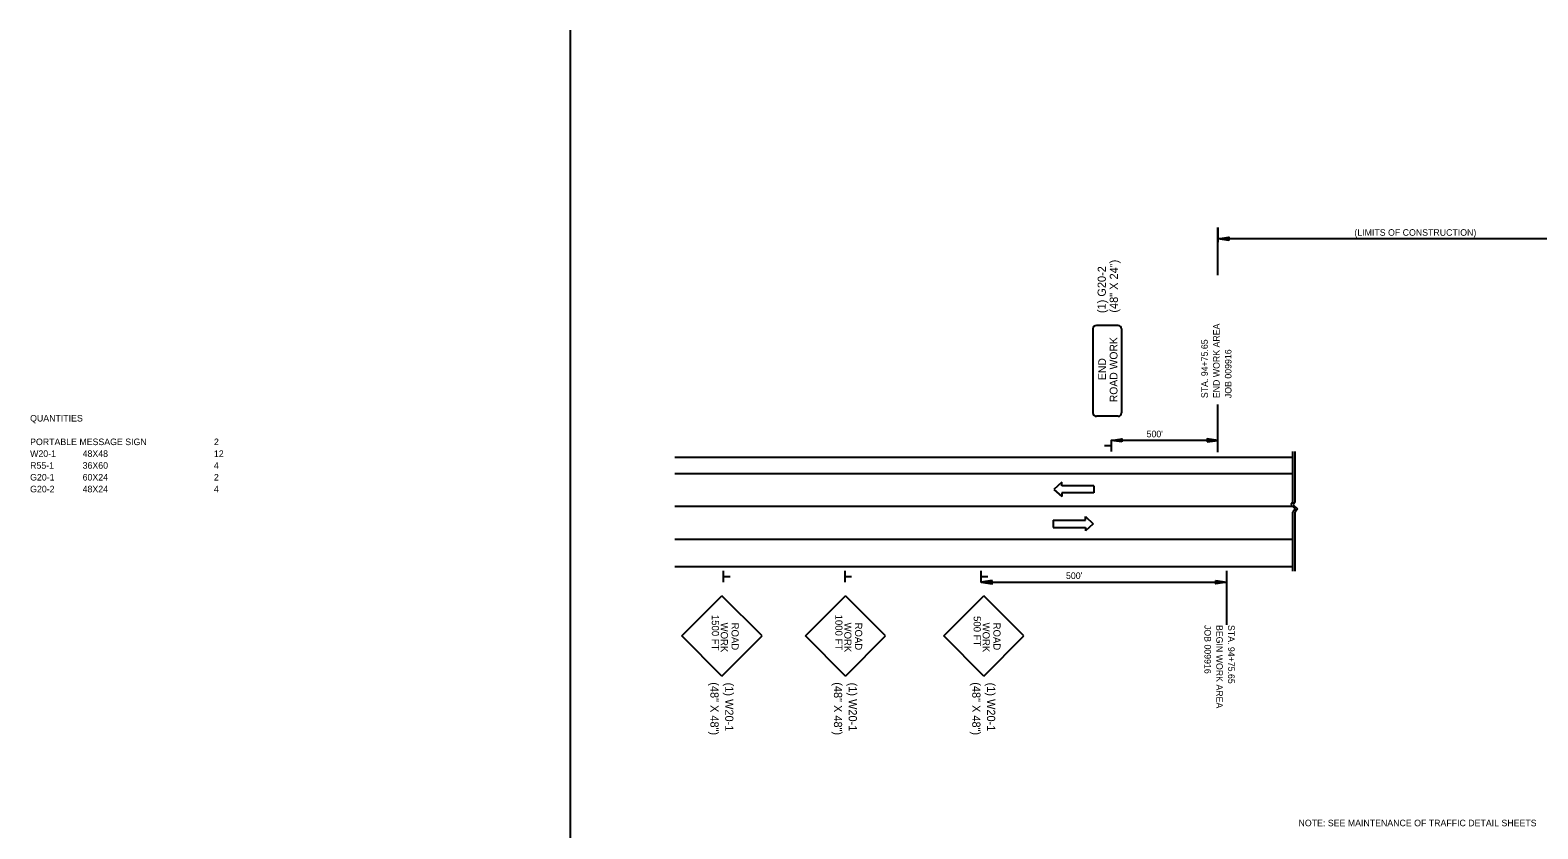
# Model space of a CAD drawing. Extents: x -900 to -62, y -12423 to -11428.
# Drawn here: x -900 to -349, y -12134 to -11842 of the extents above; entities that cross this region are included whole.
import ezdxf

# ---------------------------------------------------------------- set-up
doc = ezdxf.new("R2010")
doc.units = 0
for name, color, linetype in [('1', 7, 'Continuous'), ('Level 1', 7, 'Continuous'), ('R_MOT', 7, 'Continuous')]:
    doc.layers.add(name, color=color, linetype=linetype)

msp = doc.modelspace()

# ---------------------------------------------------------------- linework, layer by layer
at = {"layer": '1'}
for p, q in [((-465.9, -11931.22), (-465.9, -11913.78)), ((-465.9, -11913.78), (-465.9, -11919.03)), ((-319.31, -11917.87), (-465.9, -11917.87)), ((-465.9, -11995.93), (-465.9, -11978.49)), ((-465.9, -11991.59), (-504.98, -11991.59)), ((-504.97, -11991.61), (-504.97, -11995.67)), ((-664.49, -11997.69), (-438.5, -11997.69)), ((-504.97, -11993.64), (-507.34, -11993.64)), ((-438.5, -12014.03), (-438.5, -11995.69)), ((-437.63, -12014.03), (-437.63, -11995.69)), ((-664.49, -12003.69), (-438.5, -12003.69)), ((-438.5, -12014.03), (-439.26, -12015.18)), ((-439.26, -12015.18), (-437.73, -12016.71)), ((-437.63, -12014.03), (-438.39, -12015.18)), ((-438.39, -12015.18), (-436.86, -12016.71)), ((-664.49, -12015.69), (-438.75, -12015.69)), ((-437.73, -12016.71), (-438.5, -12017.85)), ((-438.5, -12039.43), (-438.5, -12017.85)), ((-436.86, -12016.71), (-437.63, -12017.85)), ((-437.63, -12039.43), (-437.63, -12017.85)), ((-664.49, -12027.69), (-438.5, -12027.69)), ((-664.49, -12037.69), (-438.5, -12037.69)), ((-646.62, -12043.42), (-646.62, -12039.36)), ((-646.62, -12041.39), (-644.26, -12041.39)), ((-602.22, -12043.42), (-602.22, -12039.36)), ((-602.22, -12041.39), (-599.86, -12041.39)), ((-552.45, -12043.42), (-552.45, -12039.36)), ((-552.45, -12041.39), (-550.09, -12041.39)), ((-462.72, -12059.14), (-462.72, -12039.36)), ((-552.45, -12043.43), (-462.72, -12043.43))]:
    msp.add_line(p, q, dxfattribs=at)
for points in [[(-461.94, -11918.47), (-465.9, -11917.87), (-461.94, -11917.27)], [(-501.02, -11992.19), (-504.98, -11991.59), (-501.02, -11990.99)], [(-469.86, -11992.19), (-465.9, -11991.59), (-469.86, -11990.99)], [(-548.49, -12042.83), (-552.45, -12043.43), (-548.49, -12044.03)], [(-466.68, -12042.83), (-462.72, -12043.43), (-466.68, -12044.03)]]:
    msp.add_lwpolyline(points, close=True, dxfattribs=at)
at = {"layer": 'Level 1'}
msp.add_line((-702.63, -12252.44), (-702.63, -11841.52), dxfattribs=at)
at = {"layer": 'R_MOT'}
for p, q in [((-511.6, -11950.84), (-511.6, -11981.55)), ((-502.42, -11949.59), (-510.35, -11949.59)), ((-501.17, -11950.84), (-501.17, -11981.55)), ((-502.42, -11982.8), (-510.35, -11982.8)), ((-522.99, -12006.93), (-525.87, -12009.54)), ((-525.87, -12009.54), (-522.99, -12012.16)), ((-522.99, -12008.24), (-522.99, -12006.93)), ((-511.24, -12008.24), (-522.99, -12008.24)), ((-511.24, -12008.24), (-511.24, -12010.85)), ((-511.24, -12010.85), (-522.99, -12010.85)), ((-522.99, -12010.85), (-522.99, -12012.16)), ((-526.14, -12020.81), (-514.39, -12020.81)), ((-526.14, -12020.81), (-526.14, -12023.43)), ((-514.39, -12020.81), (-514.39, -12019.51)), ((-514.39, -12019.51), (-511.52, -12022.12)), ((-526.14, -12023.43), (-514.39, -12023.43)), ((-511.52, -12022.12), (-514.39, -12024.74)), ((-514.39, -12023.43), (-514.39, -12024.74)), ((-661.87, -12063.15), (-647.23, -12048.49)), ((-632.57, -12063.15), (-647.23, -12048.49)), ((-616.72, -12063.15), (-602.07, -12048.49)), ((-587.41, -12063.15), (-602.07, -12048.49)), ((-566.15, -12063.15), (-551.5, -12048.49)), ((-536.84, -12063.15), (-551.5, -12048.49)), ((-647.23, -12077.81), (-661.87, -12063.15)), ((-647.23, -12077.81), (-632.57, -12063.15)), ((-602.07, -12077.81), (-616.72, -12063.15)), ((-602.07, -12077.81), (-587.41, -12063.15)), ((-551.5, -12077.81), (-566.15, -12063.15)), ((-551.5, -12077.81), (-536.84, -12063.15))]:
    msp.add_line(p, q, dxfattribs=at)
for centre, start, end in [((-510.35, -11950.84), 90.0014, 180.0003), ((-502.42, -11950.84), 0.0003, 90.0014), ((-510.35, -11981.55), 180.0003, 270.0014), ((-502.42, -11981.55), 270.0014, 0.0003)]:
    msp.add_arc(centre, 1.25, start, end, dxfattribs=at)

# ---------------------------------------------------------------- texts
at = {"layer": '1'}
for s, p in [('(LIMITS OF CONSTRUCTION)', (-416.03, -11916.75)), ('QUANTITIES', (-900.15, -11984.7)), ('PORTABLE MESSAGE SIGN', (-900.15, -11993.34)), ('2', (-832.95, -11993.34)), ("500'", (-492, -11990.47)), ('W20-1', (-900.15, -11997.66)), ('48X48', (-880.95, -11997.66)), ('12', (-832.95, -11997.66)), ('G20-1', (-900.15, -12006.3)), ('R55-1', (-900.15, -12001.98)), ('36X60', (-880.95, -12001.98)), ('60X24', (-880.95, -12006.3)), ('4', (-832.95, -12001.98)), ('2', (-832.95, -12006.3)), ('G20-2', (-900.15, -12010.62)), ('48X24', (-880.95, -12010.62)), ('4', (-832.95, -12010.62)), ('NOTE: SEE MAINTENANCE OF TRAFFIC DETAIL SHEETS', (-436.45, -12132.78))]:
    msp.add_text(s, height=2.4, dxfattribs=at).set_placement(p)
for s, rotation, p in [('END WORK AREA ', 90, (-465.28, -11976.15)), ('STA. 94+75.65', 90, (-469.6, -11976.15)), ('JOB 009916', 90, (-460.96, -11976.15)), ("500'", 360, (-521.46, -12042.31)), ('JOB 009916', 270, (-470.85, -12059.14)), ('BEGIN WORK AREA ', 270, (-466.53, -12059.14)), ('STA. 94+75.65', 270, (-462.21, -12059.14))]:
    msp.add_text(s, height=2.4, rotation=rotation, dxfattribs=at).set_placement(p)
at = {"layer": 'R_MOT'}
for s, height, rotation, p in [('(48" X 24")', 3, 89.6927, (-502.52, -11944.87)), ('(1) G20-2', 3, 89.6927, (-506.95, -11945.05)), ('ROAD WORK', 2.835, 90.0006, (-502.64, -11977.64)), ('END', 2.835, 90.0006, (-506.83, -11969.53)), ('1500 FT', 2.613, 270, (-650.94, -12055.46)), ('WORK', 2.613, 270, (-647.67, -12058.27)), ('ROAD', 2.613, 270.0004, (-643.73, -12058.28)), ('1000 FT', 2.613, 270, (-605.79, -12055.36)), ('WORK', 2.613, 270, (-602.52, -12058.27)), ('ROAD', 2.613, 270.0004, (-598.58, -12058.28)), ('500 FT', 2.613, 270, (-555.22, -12055.89)), ('WORK', 2.613, 270, (-551.95, -12058.27)), ('ROAD', 2.613, 270.0004, (-548, -12058.28)), ('(48" X 48")', 3, 270, (-651.45, -12080.1)), ('(1) W20-1', 3, 270, (-646.05, -12080.23)), ('(48" X 48")', 3, 270, (-606.3, -12080.1)), ('(1) W20-1', 3, 270, (-600.9, -12080.23)), ('(48" X 48")', 3, 270, (-555.73, -12080.1)), ('(1) W20-1', 3, 270, (-550.33, -12080.23))]:
    msp.add_text(s, height=height, rotation=rotation, dxfattribs=at).set_placement(p)

doc.saveas('drawing.dxf')
